// Mitsubishi GX Works2 project: 66.用子程序做选择按钮   PLC: FX3U/FX3UC

PROGRAM MAIN
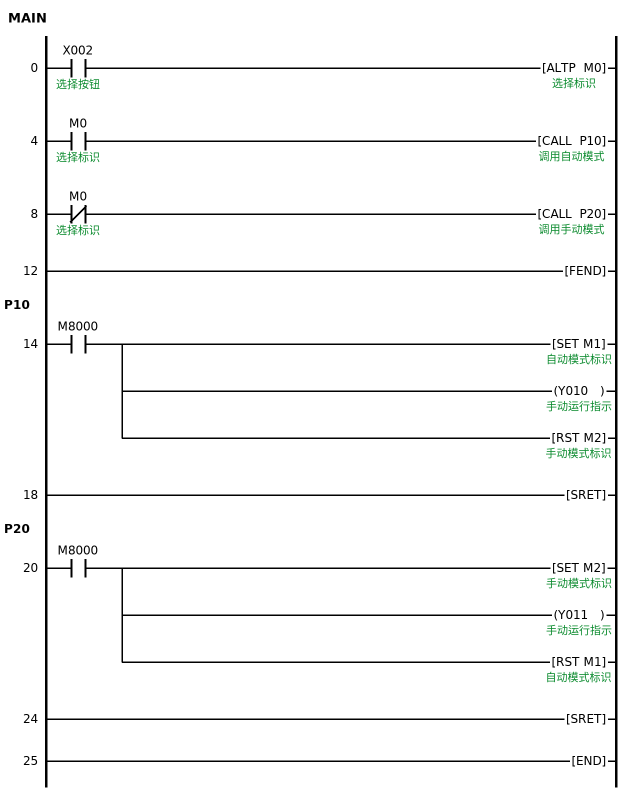
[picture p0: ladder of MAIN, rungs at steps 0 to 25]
0     LD      X002  ; 选择按钮
      ALTP    M0  ; 选择标识
4     LD      M0  ; 选择标识
      CALL    P10  ; 调用自动模式
8     LDI     M0  ; 选择标识
      CALL    P20  ; 调用手动模式
12    FEND
      P10
14    LD      M8000
      SET     M1  ; 自动模式标识
      OUT     Y010  ; 手动运行指示
      RST     M2  ; 手动模式标识
18    SRET
      P20
20    LD      M8000
      SET     M2  ; 手动模式标识
      OUT     Y011  ; 手动运行指示
      RST     M1  ; 自动模式标识
24    SRET
25    END
END_PROGRAM

// device comments not shown above
X014  ; 模式选择按钮
